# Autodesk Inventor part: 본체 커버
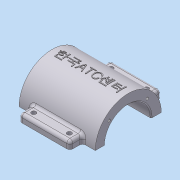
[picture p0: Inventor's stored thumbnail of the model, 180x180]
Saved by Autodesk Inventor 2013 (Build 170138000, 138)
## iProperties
Company: 한국ATC센터
Created: 2009-02
Part Number: 본체 커버
Document SubType Name: Modeling
Designer: KYOUNG IL JANG
Density: 2.71 g/cm^3
Mass: 199.244 g
Surface Area: 195.422 cm^2
Volume: 73.5218 cm^3
Material: 알루미늄-6061
Vendor: CBT Solutions
Author: KYOUNG IL JANG
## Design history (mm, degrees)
sketch "스케치1"
  geometry: L1 (-45, 40)-(45, 40); L2 (45, 40)-(45, -40); L3 (45, -40)-(-45, -40); L4 (-45, -40)-(-45, 40); 3 further points
  constraints: 8 end point, 2 midpoint, 2 parallel, 1 horizontal, 1 horizontal alignment, 1 perpendicular, 1 vertical alignment
  dimensions: "d0" = 90 distance of L2.end L3.end; "d1" = 80 distance of L1.end L2.end
extrude "돌출1" new body sketch "스케치1" distance "d2" = 10; taper "d3" = 0 deg
sketch "스케치2"
  geometry: L1 (40, 0)-(-40, 0) reference; C1 r 32.5 at (0, 80); 2 further points
  constraints: 1 centre point, 1 midpoint, 1 vertical alignment
  dimensions: "d4" = 65 diameter of C1; "d5" = 80 distance from line of C1.centre L1
extrude "돌출2" join sketch "스케치2" stored distance "d6" = 75; taper "d7" = 0 deg
sketch "스케치3"
  geometry: L1 (-7.5, -20)-(7.5, -20); L2 (7.5, 20)-(-7.5, 20); A1 r 20 centre (7.5, 0) between (7.5, -20) and (7.5, 20); A2 r 20 centre (-7.5, 0) between (-7.5, 20) and (-7.5, -20); 2 further points
  constraints: 4 end point, 4 point on circle, 4 tangent, 2 centre point, 1 horizontal, 1 horizontal alignment, 1 midpoint, 1 parallel, 1 vertical alignment
  dimensions: "d8" = 20 radius of A2; "d9" = 55 dimension on A1 A2
extrude "돌출3" join sketch "스케치3" stored distance "d10" = 75; taper "d11" = 0 deg
fillet "모깎기1" dims "d12" = 10
sketch "스케치4"
  geometry: L1 (-45, 0)-(-45, 10) reference; L2 (37.5, 47.5)-(-37.5, 47.5) reference; L3 (-45, 10)-(-27.513, 47.5); 1 further point
  constraints: 2 end point, 1 point on line
  dimensions: "d13" = 25 deg angle of L3 L1
sketch "스케치5"
  geometry: L1 (-40, 0)-(-40, 10) reference; L2 (-40, 10)-(-22.912, 56.95); 2 further points
  constraints: 2 end point, 2 other
  dimensions: "d14" = 20 deg angle of L2 L1
feature "리브1" dims "d15" = 1, "d16" = 6, "d17" = 0
feature "리브2" dims "d18" = 1, "d19" = 6, "d20" = 0
fillet "모깎기2" dims "d21" = 3
fillet "모깎기3" dims "d22" = 3
fillet "모깎기4" dims "d23" = 3
fillet "모깎기5" dims "d24" = 3
fillet "모깎기6" dims "d25" = 3
fillet "모깎기7" dims "d26" = 3
fillet "모깎기8" dims "d27" = 3
sketch "스케치6"
  geometry: A1 r 10 centre (35, -30) between (35, -40) and (45, -30) reference; 1 further point
hole "구멍1" sketch "스케치6" at (35, -30) diameter "d28" = 10; stored, may be unused: countersink angle "d32" = 90 deg, drill point angle "d34" = 118 deg; dims "d29" = 6, "d30" = 4, "d31" = 2, "d33" = 8
hole "구멍2" diameter "d37" = 45; stored, may be unused: countersink angle "d41" = 90 deg, drill point angle "d43" = 118 deg; dims "d35" = 10, "d36" = 10, "d38" = 6, "d39" = 4, "d40" = 2, "d42" = 8
sketch "스케치7"
  geometry: C1 r 22.5 at (0, 0) reference; 2 further points
  dimensions: "d44" = 135 deg dimension on C1.centre point (-18.738, 18.738) point (80, 0); "d45" = 26.5 distance of point (-18.738, 18.738) C1.centre
hole "구멍3" sketch "스케치7" at (-18.738, 18.738) diameter "d46" = 2.459; stored, may be unused: countersink angle "d50" = 90 deg, drill point angle "d52" = 118 deg; dims "d47" = 8, "d48" = 4, "d49" = 2, "d51" = 10
node "작업 평면1"
chamfer "모따기1" distance "d69" = 1; stored, may be unused: second distance "d70" = 2, angle "d71" = 45 deg
sketch "스케치9"
  geometry: L1 (-31.623, 87.5)-(-45, 87.5); L2 (-45, 87.5)-(-45, 72.5); L3 (-45, 72.5)-(-31.623, 72.5); A1 r 32.5 centre (0, 80) between (-31.623, 87.5) and (-31.623, 72.5) reference; 1 further point
  constraints: 6 end point, 2 parallel, 2 point on circle, 1 horizontal, 1 perpendicular
  dimensions: "d73" = 15 distance of L1.end L2.end; "d74" = 45 distance from line of A1.centre L2
extrude "돌출5" join sketch "스케치9" stored distance "d75" = 50; taper "d76" = 0 deg
fillet "모깎기10" dims "d77" = 3
fillet "모깎기11" dims "d78" = 3
sketch "스케치10"
  geometry: L1 (100.378, 66.389)-(0, 66.389); L2 (0, 66.389)-(0, -76.978); L3 (0, -76.978)-(100.378, -76.978); L4 (100.378, -76.978)-(100.378, 66.389); C1 r 32.5 at (0, 0) reference; 1 further point
  constraints: 8 end point, 2 parallel, 1 horizontal, 1 perpendicular, 1 point on line
extrude "돌출6" cut sketch "스케치10" stored distance "d79" = 10; taper "d80" = 0 deg
sketch "스케치11"
  geometry: C1 r 1.621 at (4.5, 4) reference; C2 r 1.621 at (39.5, 4) reference; 1 further point
hole "구멍5" sketch "스케치11" at (39.5, 4), (4.5, 4) diameter "d81" = 4.5; stored, may be unused: countersink angle "d85" = 90 deg, drill point angle "d87" = 118 deg; dims "d82" = 6, "d83" = 4, "d84" = 2, "d86" = 8
node "작업 평면2"
sketch "스케치12"
  geometry: 2 further points
  constraints: 1 coincident, 1 other
feature "엠보싱1" sketch "스케치12" dims "d8" = 20, "d9" = 55, "d88" = 0.5, "d89" = 0
node "솔리드1"
mirror "대칭1"
mirror "대칭2"
mirror "대칭3"
mirror "대칭4"
pattern_circular "원형 패턴1" dims angle "d54" = 360 deg
mirror "대칭5"
mirror "대칭6"
mirror "대칭7"
node "참조1"
node "참조2"
other parameters: "d56" = -117
